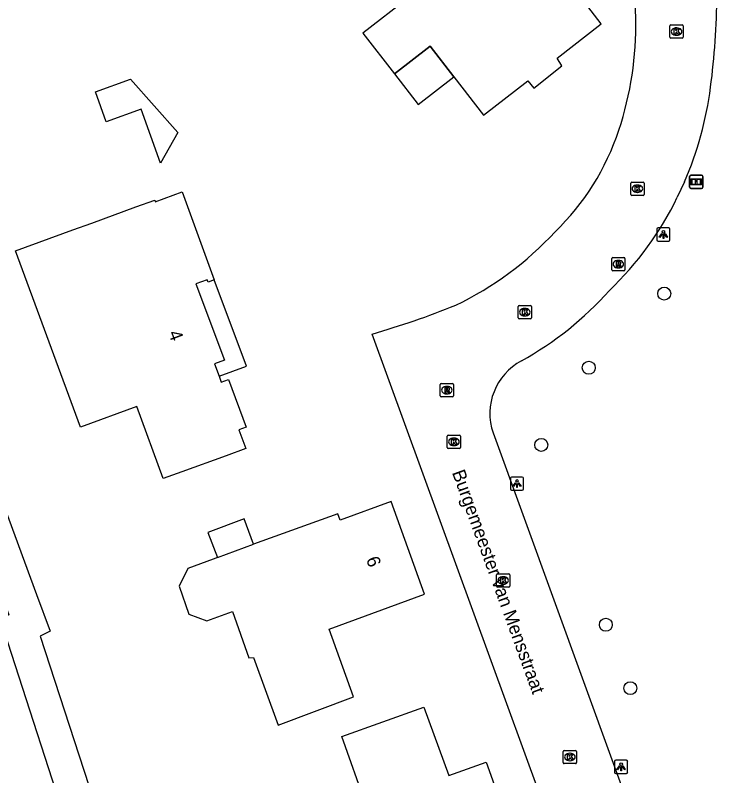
# Model space of a CAD drawing. Extents: x 159503 to 160347, y 382525 to 383272.
# Drawn here: x 159751.6 to 159804.6, y 382852.9 to 382910.4 of the extents above; entities that cross this region are included whole.
import ezdxf

# ---------------------------------------------------------------- set-up
doc = ezdxf.new("R2010")
doc.units = 0
for name, color, linetype in [('IMGEO_Boom', 7, 'Continuous'), ('IMGEO_Groenvoorziening', 7, 'Continuous'), ('IMGEO_Informatiebord', 7, 'Continuous'), ('IMGEO_Kolk', 7, 'Continuous'), ('IMGEO_Lichtpunt', 7, 'Continuous'), ('IMGEO_Openbare_ruimte_label', 7, 'Continuous'), ('IMGEO_Pand', 7, 'Continuous'), ('IMGEO_Pand_nummerreeks', 7, 'Continuous'), ('IMGEO_Pand_overbouw', 7, 'Continuous'), ('IMGEO_Rijbaan_lokaal_open', 7, 'Continuous'), ('IMGEO_Rioolput', 7, 'Continuous')]:
    doc.layers.add(name, color=color, linetype=linetype)

msp = doc.modelspace()

# ---------------------------------------------------------------- linework, layer by layer
at = {"layer": 'IMGEO_Boom'}
for centre in [(159800.667, 382889.32), (159794.962, 382883.71), (159791.37, 382877.879), (159796.25, 382864.274), (159798.106, 382859.48)]:
    msp.add_circle(centre, 0.489, dxfattribs=at)
at = {"layer": 'IMGEO_Groenvoorziening'}
for points in [[(159730.546, 382899.75), (159741.202, 382899.547), (159744.626, 382889.831), (159753.21, 382866.555), (159754.229, 382863.79), (159753.482, 382863.418), (159757.881, 382849.879)], [(159731.353, 382897.234), (159739.421, 382897.08), (159751.108, 382865.029), (159750.438, 382864.695), (159756.337, 382846.542), (159757.115, 382846.862), (159769.976, 382810.359), (159802.405, 382822.292)]]:
    msp.add_lwpolyline(points, dxfattribs=at)
at = {"layer": 'IMGEO_Informatiebord'}
for p, q in [((159802.591, 382897.372), (159802.591, 382898.172)), ((159802.591, 382898.172), (159802.591, 382897.372)), ((159802.691, 382898.272), (159803.481, 382898.272)), ((159803.481, 382898.272), (159802.691, 382898.272)), ((159803.581, 382898.172), (159803.581, 382897.372)), ((159803.581, 382897.372), (159803.581, 382898.172)), ((159803.481, 382897.272), (159802.691, 382897.272)), ((159802.691, 382897.272), (159803.481, 382897.272))]:
    msp.add_line(p, q, dxfattribs=at)
for points in [[(159802.692, 382898.004), (159803.48, 382898.004), (159803.48, 382897.54), (159802.692, 382897.54), (159802.692, 382898.004)], [(159802.757, 382897.939), (159802.757, 382897.605), (159803.032, 382897.605), (159803.033, 382897.818), (159803.137, 382897.819), (159803.138, 382897.605), (159803.415, 382897.605), (159803.415, 382897.939), (159803.139, 382897.939), (159803.139, 382897.859), (159803.033, 382897.859), (159803.033, 382897.939), (159802.757, 382897.939)]]:
    msp.add_lwpolyline(points, dxfattribs=at)
for centre, start, end in [((159802.691, 382898.172), 90, 180), ((159802.691, 382898.172), 90, 180), ((159803.481, 382898.172), 0, 90), ((159803.481, 382898.172), 360, 90), ((159802.691, 382897.372), 180, 270), ((159802.691, 382897.372), 180, 270), ((159803.481, 382897.372), 270, 0), ((159803.481, 382897.372), 270, 0)]:
    msp.add_arc(centre, 0.1, start, end, dxfattribs=at)
at = {"layer": 'IMGEO_Kolk'}
for p, q in [((159801.102, 382908.71), (159801.102, 382909.562)), ((159801.177, 382909.636), (159802.029, 382909.636)), ((159801.59, 382909.416), (159801.615, 382909.416)), ((159802.103, 382909.562), (159802.103, 382908.71)), ((159801.613, 382908.856), (159801.588, 382908.856)), ((159802.029, 382908.636), (159801.177, 382908.636)), ((159798.213, 382897.751), (159799.065, 382897.751)), ((159798.138, 382896.825), (159798.138, 382897.677)), ((159798.626, 382897.531), (159798.651, 382897.531)), ((159799.139, 382897.677), (159799.139, 382896.825)), ((159799.065, 382896.751), (159798.213, 382896.751)), ((159798.649, 382896.971), (159798.624, 382896.971)), ((159789.625, 382887.488), (159789.625, 382888.34)), ((159789.7, 382888.414), (159790.552, 382888.414)), ((159790.113, 382888.194), (159790.138, 382888.194)), ((159790.626, 382888.34), (159790.626, 382887.488)), ((159790.552, 382887.414), (159789.7, 382887.414)), ((159790.136, 382887.634), (159790.111, 382887.634)), ((159784.261, 382877.685), (159784.261, 382878.537)), ((159784.336, 382878.611), (159785.188, 382878.611)), ((159784.749, 382878.391), (159784.774, 382878.391)), ((159785.262, 382878.537), (159785.262, 382877.685)), ((159785.188, 382877.611), (159784.336, 382877.611)), ((159784.772, 382877.831), (159784.747, 382877.831)), ((159787.99, 382867.202), (159787.99, 382868.054)), ((159788.065, 382868.128), (159788.917, 382868.128)), ((159788.478, 382867.908), (159788.503, 382867.908)), ((159788.991, 382868.054), (159788.991, 382867.202)), ((159788.501, 382867.348), (159788.476, 382867.348)), ((159788.917, 382867.128), (159788.065, 382867.128)), ((159793.035, 382853.848), (159793.035, 382854.7)), ((159793.11, 382854.774), (159793.962, 382854.774)), ((159794.036, 382854.7), (159794.036, 382853.848)), ((159793.523, 382854.554), (159793.548, 382854.554)), ((159793.962, 382853.774), (159793.11, 382853.774)), ((159793.546, 382853.994), (159793.521, 382853.994))]:
    msp.add_line(p, q, dxfattribs=at)
for points in [[(159801.102, 382908.71), (159801.102, 382909.562)], [(159801.177, 382909.636), (159802.029, 382909.636)], [(159801.423, 382909.336), (159801.546, 382909.336), (159801.546, 382909.185), (159801.676, 382909.336), (159801.84, 382909.336), (159801.694, 382909.185), (159801.847, 382908.936), (159801.695, 382908.936), (159801.61, 382909.1), (159801.546, 382909.033), (159801.546, 382908.936), (159801.423, 382908.936), (159801.423, 382909.336)], [(159802.103, 382909.562), (159802.103, 382908.71)], [(159802.029, 382908.636), (159801.177, 382908.636)], [(159798.213, 382897.751), (159799.065, 382897.751)], [(159798.138, 382896.825), (159798.138, 382897.677)], [(159798.459, 382897.451), (159798.582, 382897.451), (159798.582, 382897.3), (159798.712, 382897.451), (159798.876, 382897.451), (159798.73, 382897.3), (159798.883, 382897.051), (159798.731, 382897.051), (159798.646, 382897.215), (159798.582, 382897.148), (159798.582, 382897.051), (159798.459, 382897.051), (159798.459, 382897.451)], [(159799.139, 382897.677), (159799.139, 382896.825)], [(159799.065, 382896.751), (159798.213, 382896.751)], [(159789.625, 382887.488), (159789.625, 382888.34)], [(159789.7, 382888.414), (159790.552, 382888.414)], [(159789.946, 382888.114), (159790.069, 382888.114), (159790.069, 382887.963), (159790.199, 382888.114), (159790.363, 382888.114), (159790.217, 382887.963), (159790.37, 382887.714), (159790.218, 382887.714), (159790.133, 382887.878), (159790.069, 382887.811), (159790.069, 382887.714), (159789.946, 382887.714), (159789.946, 382888.114)], [(159790.626, 382888.34), (159790.626, 382887.488)], [(159790.552, 382887.414), (159789.7, 382887.414)], [(159784.261, 382877.685), (159784.261, 382878.537)], [(159784.336, 382878.611), (159785.188, 382878.611)], [(159784.582, 382878.311), (159784.705, 382878.311), (159784.705, 382878.16), (159784.835, 382878.311), (159784.999, 382878.311), (159784.853, 382878.16), (159785.006, 382877.911), (159784.854, 382877.911), (159784.769, 382878.075), (159784.705, 382878.008), (159784.705, 382877.911), (159784.582, 382877.911), (159784.582, 382878.311)], [(159785.262, 382878.537), (159785.262, 382877.685)], [(159785.188, 382877.611), (159784.336, 382877.611)], [(159787.99, 382867.202), (159787.99, 382868.054)], [(159788.065, 382868.128), (159788.917, 382868.128)], [(159788.311, 382867.828), (159788.434, 382867.828), (159788.434, 382867.677), (159788.564, 382867.828), (159788.728, 382867.828), (159788.582, 382867.677), (159788.735, 382867.428), (159788.583, 382867.428), (159788.498, 382867.592), (159788.434, 382867.525), (159788.434, 382867.428), (159788.311, 382867.428), (159788.311, 382867.828)], [(159788.991, 382868.054), (159788.991, 382867.202)], [(159788.917, 382867.128), (159788.065, 382867.128)], [(159793.035, 382853.848), (159793.035, 382854.7)], [(159793.11, 382854.774), (159793.962, 382854.774)], [(159794.036, 382854.7), (159794.036, 382853.848)], [(159793.356, 382854.474), (159793.479, 382854.474), (159793.479, 382854.323), (159793.609, 382854.474), (159793.773, 382854.474), (159793.627, 382854.323), (159793.78, 382854.074), (159793.628, 382854.074), (159793.543, 382854.238), (159793.479, 382854.171), (159793.479, 382854.074), (159793.356, 382854.074), (159793.356, 382854.474)], [(159793.962, 382853.774), (159793.11, 382853.774)]]:
    msp.add_lwpolyline(points, dxfattribs=at)
for centre, start, end in [((159801.179, 382909.56), 91.55205, 178.44795), ((159801.179, 382909.56), 91.55205, 178.44795), ((159802.027, 382909.56), 1.55205, 88.44795), ((159802.027, 382909.56), 1.55205, 88.44795), ((159801.179, 382908.712), 181.55205, 268.44795), ((159801.179, 382908.712), 181.55205, 268.44795), ((159802.027, 382908.712), 271.55205, 358.44795), ((159802.027, 382908.712), 271.55205, 358.44795), ((159798.215, 382897.675), 91.55205, 178.44795), ((159798.215, 382897.675), 91.55205, 178.44795), ((159799.063, 382897.675), 1.55205, 88.44795), ((159799.063, 382897.675), 1.55205, 88.44795), ((159798.215, 382896.827), 181.55205, 268.44795), ((159798.215, 382896.827), 181.55205, 268.44795), ((159799.063, 382896.827), 271.55205, 358.44795), ((159799.063, 382896.827), 271.55205, 358.44795), ((159789.702, 382888.338), 91.55205, 178.44795), ((159789.702, 382888.338), 91.55205, 178.44795), ((159790.55, 382888.338), 1.55205, 88.44795), ((159790.55, 382888.338), 1.55205, 88.44795), ((159789.702, 382887.49), 181.55205, 268.44795), ((159789.702, 382887.49), 181.55205, 268.44795), ((159790.55, 382887.49), 271.55205, 358.44795), ((159790.55, 382887.49), 271.55205, 358.44795), ((159784.338, 382878.535), 91.55205, 178.44795), ((159784.338, 382878.535), 91.55205, 178.44795), ((159785.186, 382878.535), 1.55205, 88.44795), ((159785.186, 382878.535), 1.55205, 88.44795), ((159784.338, 382877.687), 181.55205, 268.44795), ((159784.338, 382877.687), 181.55205, 268.44795), ((159785.186, 382877.687), 271.55205, 358.44795), ((159785.186, 382877.687), 271.55205, 358.44795), ((159788.067, 382868.052), 91.55205, 178.44795), ((159788.067, 382868.052), 91.55205, 178.44795), ((159788.915, 382868.052), 1.55205, 88.44795), ((159788.915, 382868.052), 1.55205, 88.44795), ((159788.067, 382867.204), 181.55205, 268.44795), ((159788.067, 382867.204), 181.55205, 268.44795), ((159788.915, 382867.204), 271.55205, 358.44795), ((159788.915, 382867.204), 271.55205, 358.44795), ((159793.112, 382854.698), 91.55205, 178.44795), ((159793.112, 382854.698), 91.55205, 178.44795), ((159793.96, 382854.698), 1.55205, 88.44795), ((159793.96, 382854.698), 1.55205, 88.44795), ((159793.112, 382853.85), 181.55205, 268.44795), ((159793.112, 382853.85), 181.55205, 268.44795), ((159793.96, 382853.85), 271.55205, 358.44795), ((159793.96, 382853.85), 271.55205, 358.44795)]:
    msp.add_arc(centre, 0.0765, start, end, dxfattribs=at)
for centre, major_axis, ratio, start_param, end_param in [((159801.589, 382909.136), (-0.387, 0.002), 0.722429, 4.712389, 7.853982), ((159801.614, 382909.136), (-0.39, 0.002), 0.717154, 1.570796, 4.712389), ((159798.625, 382897.251), (-0.387, 0.002), 0.722429, 4.712389, 7.853982), ((159798.65, 382897.251), (-0.39, 0.002), 0.717154, 1.570796, 4.712389), ((159790.112, 382887.914), (-0.387, 0.002), 0.722429, 4.712389, 7.853982), ((159790.137, 382887.914), (-0.39, 0.002), 0.717154, 1.570796, 4.712389), ((159784.748, 382878.111), (-0.387, 0.002), 0.722429, 4.712389, 7.853982), ((159784.773, 382878.111), (-0.39, 0.002), 0.717154, 1.570796, 4.712389), ((159788.477, 382867.628), (-0.387, 0.002), 0.722429, 4.712389, 7.853982), ((159788.502, 382867.628), (-0.39, 0.002), 0.717154, 1.570796, 4.712389), ((159793.522, 382854.274), (-0.387, 0.002), 0.722429, 4.712389, 7.853982), ((159793.547, 382854.274), (-0.39, 0.002), 0.717154, 1.570796, 4.712389)]:
    msp.add_ellipse(centre, major_axis=major_axis, ratio=ratio, start_param=start_param, end_param=end_param, dxfattribs=at)
at = {"layer": 'IMGEO_Lichtpunt'}
for p, q in [((159801.007, 382894.286), (159800.199, 382894.286)), ((159801.007, 382894.286), (159800.199, 382894.286)), ((159800.105, 382894.191), (159800.105, 382893.384)), ((159800.105, 382894.191), (159800.105, 382893.384)), ((159801.101, 382893.384), (159801.101, 382894.191)), ((159801.101, 382893.384), (159801.101, 382894.191)), ((159800.199, 382893.29), (159801.007, 382893.29)), ((159800.199, 382893.29), (159801.007, 382893.29)), ((159789.036, 382875.352), (159789.036, 382874.545)), ((159789.036, 382875.352), (159789.036, 382874.545)), ((159789.938, 382875.447), (159789.13, 382875.447)), ((159789.938, 382875.447), (159789.13, 382875.447)), ((159790.032, 382874.545), (159790.032, 382875.352)), ((159790.032, 382874.545), (159790.032, 382875.352)), ((159789.13, 382874.451), (159789.938, 382874.451)), ((159789.13, 382874.451), (159789.938, 382874.451)), ((159797.809, 382854.034), (159797.001, 382854.034)), ((159797.809, 382854.034), (159797.001, 382854.034)), ((159796.907, 382853.939), (159796.907, 382853.132)), ((159796.907, 382853.939), (159796.907, 382853.132)), ((159797.903, 382853.132), (159797.903, 382853.939)), ((159797.903, 382853.132), (159797.903, 382853.939)), ((159797.001, 382853.038), (159797.809, 382853.038)), ((159797.001, 382853.038), (159797.809, 382853.038))]:
    msp.add_line(p, q, dxfattribs=at)
for points in [[(159800.479, 382893.855), (159800.518, 382893.827), (159800.33, 382893.565), (159800.292, 382893.592), (159800.479, 382893.855)], [(159800.581, 382893.807), (159800.628, 382893.807), (159800.628, 382893.485), (159800.581, 382893.485), (159800.581, 382893.807)], [(159800.691, 382893.827), (159800.729, 382893.854), (159800.916, 382893.592), (159800.877, 382893.564), (159800.691, 382893.827)], [(159789.41, 382875.016), (159789.449, 382874.988), (159789.261, 382874.726), (159789.223, 382874.753), (159789.41, 382875.016)], [(159789.512, 382874.968), (159789.559, 382874.968), (159789.559, 382874.646), (159789.512, 382874.646), (159789.512, 382874.968)], [(159789.622, 382874.988), (159789.66, 382875.015), (159789.847, 382874.753), (159789.808, 382874.725), (159789.622, 382874.988)], [(159797.281, 382853.603), (159797.32, 382853.575), (159797.132, 382853.313), (159797.094, 382853.34), (159797.281, 382853.603)], [(159797.383, 382853.555), (159797.43, 382853.555), (159797.43, 382853.233), (159797.383, 382853.233), (159797.383, 382853.555)], [(159797.493, 382853.575), (159797.531, 382853.602), (159797.718, 382853.34), (159797.679, 382853.312), (159797.493, 382853.575)]]:
    msp.add_lwpolyline(points, dxfattribs=at)
for centre in [(159800.604, 382893.989), (159789.535, 382875.15), (159797.406, 382853.737)]:
    msp.add_circle(centre, 0.0994, dxfattribs=at)
for centre, start, end in [((159800.199, 382894.191), 90, 180), ((159800.199, 382894.191), 90, 180), ((159801.007, 382894.191), 0, 90), ((159801.007, 382894.191), 0, 90), ((159800.199, 382893.384), 180, 270), ((159800.199, 382893.384), 180, 270), ((159801.007, 382893.384), 270, 0), ((159801.007, 382893.384), 270, 360), ((159789.13, 382875.352), 90, 180), ((159789.13, 382875.352), 90, 180), ((159789.938, 382875.352), 0, 90), ((159789.938, 382875.352), 0, 90), ((159789.13, 382874.545), 180, 270), ((159789.13, 382874.545), 180, 270), ((159789.938, 382874.545), 270, 0), ((159789.938, 382874.545), 270, 360), ((159797.001, 382853.939), 90, 180), ((159797.001, 382853.939), 90, 180), ((159797.809, 382853.939), 0, 90), ((159797.809, 382853.939), 0, 90), ((159797.001, 382853.132), 180, 270), ((159797.001, 382853.132), 180, 270), ((159797.809, 382853.132), 270, 0), ((159797.809, 382853.132), 270, 360)]:
    msp.add_arc(centre, 0.0946, start, end, dxfattribs=at)
at = {"layer": 'IMGEO_Pand'}
for points in [[(159795.905, 382909.71), (159791.354, 382915.635), (159788.06, 382913.101), (159786.645, 382912.012), (159784.784, 382914.376), (159777.868, 382909.009), (159780.26, 382905.936), (159782.968, 382908.036), (159784.766, 382905.702), (159786.989, 382902.813), (159790.348, 382905.404), (159790.798, 382904.856), (159792.921, 382906.556), (159792.571, 382907.124), (159795.905, 382909.71)], [(159762.581, 382899.19), (159761.111, 382903.271), (159758.477, 382902.322), (159757.664, 382904.58), (159760.298, 382905.529), (159763.893, 382901.5), (159762.581, 382899.19)], [(159766.629, 382890.365), (159766.17, 382890.193), (159766.103, 382890.371), (159765.26, 382890.056), (159767.416, 382884.29), (159766.669, 382883.998), (159767.007, 382883.078), (159767.172, 382882.628), (159767.726, 382882.831), (159769.048, 382879.231), (159768.494, 382879.029), (159769.017, 382877.594), (159767.542, 382877.055), (159764.194, 382875.844), (159762.78, 382875.34), (159760.774, 382880.779), (159756.533, 382879.215), (159751.617, 382892.543), (159755.938, 382894.13), (159757.376, 382894.639), (159760.708, 382895.873), (159762.138, 382896.381), (159762.182, 382896.264), (159764.216, 382897.024), (159766.629, 382890.365)], [(159766.874, 382869.353), (159766.556, 382869.235), (159764.632, 382868.52), (159763.977, 382867.195), (159764.729, 382865.078), (159766.087, 382864.568), (159768.009, 382865.276), (159769.254, 382861.771), (159769.61, 382861.8), (159771.481, 382856.693), (159777.169, 382858.827), (159775.336, 382863.944), (159782.547, 382866.591), (159780.023, 382873.596), (159776.167, 382872.186), (159775.995, 382872.653), (159769.609, 382870.363)], [(159769.609, 382870.363), (159768.897, 382872.28), (159766.164, 382871.264), (159766.874, 382869.353)], [(159766.874, 382869.353), (159769.609, 382870.363)], [(159787.196, 382853.887), (159789.832, 382846.551), (159780.443, 382843.243), (159777.762, 382850.507), (159778.141, 382850.641), (159776.283, 382855.821), (159782.488, 382858.042), (159784.384, 382852.878), (159787.196, 382853.887)]]:
    msp.add_lwpolyline(points, dxfattribs=at)
at = {"layer": 'IMGEO_Pand_overbouw'}
for points in [[(159780.26, 382905.936), (159782.065, 382903.608), (159784.766, 382905.702), (159782.968, 382908.036)], [(159766.629, 382890.365), (159766.17, 382890.193), (159766.103, 382890.371), (159765.26, 382890.056), (159767.416, 382884.29), (159766.669, 382883.998), (159767.007, 382883.078), (159769.069, 382883.838)]]:
    msp.add_lwpolyline(points, close=True, dxfattribs=at)
at = {"layer": 'IMGEO_Rijbaan_lokaal_open'}
for points in [[(159798.523, 382910.128), (159798.515, 382910.384), (159798.504, 382910.543), (159798.494, 382910.746), (159798.488, 382910.949)], [(159802.201, 382897.773), (159801.659, 382896.603)], [(159800.223, 382826.817), (159778.58, 382886.258)], [(159787.725, 382878.782), (159799.163, 382847.358), (159800.276, 382844.273)]]:
    msp.add_lwpolyline(points, dxfattribs=at)
for centre, radius, start, end in [((159750.82, 382912.013), 53.823, 352.42978, 359.88104), ((159773.358, 382909.643), 25.17, 341.55762, 1.103), ((159777.819, 382908.349), 26.577, 336.55098, 352.59185), ((159779.308, 382907.576), 18.872, 313.97884, 341.79753), ((159779.385, 382907.464), 24.781, 313.73961, 334.00564), ((159774.202, 382910.777), 24.763, 295.60595, 317.33852), ((159777.508, 382906.485), 25.453, 299.05205, 318.32008), ((159760.634, 382948.361), 64.644, 286.11789, 292.05166), ((159792.011, 382880.245), 4.529, 118.23992, 198.85096)]:
    msp.add_arc(centre, radius, start, end, dxfattribs=at)
at = {"layer": 'IMGEO_Rioolput'}
for p, q in [((159796.774, 382892.046), (159797.626, 382892.046)), ((159796.699, 382891.12), (159796.699, 382891.972)), ((159797.187, 382891.826), (159797.212, 382891.826)), ((159797.7, 382891.972), (159797.7, 382891.12)), ((159797.626, 382891.046), (159796.774, 382891.046)), ((159797.21, 382891.266), (159797.185, 382891.266)), ((159783.729, 382881.594), (159783.729, 382882.446)), ((159783.804, 382882.52), (159784.656, 382882.52)), ((159784.217, 382882.3), (159784.242, 382882.3)), ((159784.73, 382882.446), (159784.73, 382881.594)), ((159784.24, 382881.74), (159784.215, 382881.74)), ((159784.656, 382881.52), (159783.804, 382881.52))]:
    msp.add_line(p, q, dxfattribs=at)
for points in [[(159796.774, 382892.046), (159797.626, 382892.046)], [(159796.699, 382891.12), (159796.699, 382891.972)], [(159797.288, 382891.744), (159797.036, 382891.746), (159797.036, 382891.346)], [(159797.036, 382891.346), (159797.16, 382891.346), (159797.16, 382891.508), (159797.171, 382891.508)], [(159797.214, 382891.665), (159797.16, 382891.665), (159797.16, 382891.584)], [(159797.16, 382891.584), (159797.212, 382891.584)], [(159797.218, 382891.479), (159797.289, 382891.346), (159797.429, 382891.346), (159797.364, 382891.472)], [(159797.7, 382891.972), (159797.7, 382891.12)], [(159797.626, 382891.046), (159796.774, 382891.046)], [(159783.729, 382881.594), (159783.729, 382882.446)], [(159783.804, 382882.52), (159784.656, 382882.52)], [(159784.318, 382882.218), (159784.066, 382882.22), (159784.066, 382881.82)], [(159784.73, 382882.446), (159784.73, 382881.594)], [(159784.066, 382881.82), (159784.19, 382881.82), (159784.19, 382881.982), (159784.201, 382881.982)], [(159784.244, 382882.139), (159784.19, 382882.139), (159784.19, 382882.058)], [(159784.19, 382882.058), (159784.242, 382882.058)], [(159784.248, 382881.953), (159784.319, 382881.82), (159784.459, 382881.82), (159784.394, 382881.946)], [(159784.656, 382881.52), (159783.804, 382881.52)]]:
    msp.add_lwpolyline(points, dxfattribs=at)
for centre, radius, start, end in [((159796.776, 382891.97), 0.0765, 91.55205, 178.44795), ((159796.776, 382891.97), 0.0765, 91.55205, 178.44795), ((159797.624, 382891.97), 0.0765, 1.55205, 88.44795), ((159797.624, 382891.97), 0.0765, 1.55205, 88.44795), ((159797.17, 382891.455), 0.0533, 26.02933, 88.69889), ((159797.196, 382891.773), 0.19, 274.7715, 282.96867), ((159797.22, 382891.569), 0.0964, 77.00612, 93.18647), ((159797.234, 382891.626), 0.0378, 276.66336, 79.67722), ((159797.287, 382891.634), 0.109, 350.36119, 89.41601), ((159797.285, 382891.634), 0.112, 277.58423, 350.98172), ((159797.269, 382891.419), 0.108, 29.51342, 73.79051), ((159796.776, 382891.122), 0.0765, 181.55205, 268.44795), ((159796.776, 382891.122), 0.0765, 181.55205, 268.44795), ((159797.624, 382891.122), 0.0765, 271.55205, 358.44795), ((159797.624, 382891.122), 0.0765, 271.55205, 358.44795), ((159783.806, 382882.444), 0.0765, 91.55205, 178.44795), ((159783.806, 382882.444), 0.0765, 91.55205, 178.44795), ((159784.317, 382882.108), 0.109, 350.36119, 89.41601), ((159784.654, 382882.444), 0.0765, 1.55205, 88.44795), ((159784.654, 382882.444), 0.0765, 1.55205, 88.44795), ((159784.2, 382881.929), 0.0533, 26.02933, 88.69889), ((159784.226, 382882.247), 0.19, 274.7715, 282.96867), ((159784.25, 382882.043), 0.0964, 77.00612, 93.18647), ((159784.264, 382882.1), 0.0378, 276.66336, 79.67722), ((159784.315, 382882.108), 0.112, 277.58423, 350.98172), ((159784.299, 382881.893), 0.108, 29.51342, 73.79051), ((159783.806, 382881.596), 0.0765, 181.55205, 268.44795), ((159783.806, 382881.596), 0.0765, 181.55205, 268.44795), ((159784.654, 382881.596), 0.0765, 271.55205, 358.44795), ((159784.654, 382881.596), 0.0765, 271.55205, 358.44795)]:
    msp.add_arc(centre, radius, start, end, dxfattribs=at)
for centre, major_axis, ratio, start_param, end_param in [((159797.186, 382891.546), (-0.387, 0.002), 0.722429, 4.712389, 7.853982), ((159797.211, 382891.546), (-0.39, 0.002), 0.717154, 1.570796, 4.712389), ((159784.216, 382882.02), (-0.387, 0.002), 0.722429, 4.712389, 7.853982), ((159784.241, 382882.02), (-0.39, 0.002), 0.717154, 1.570796, 4.712389)]:
    msp.add_ellipse(centre, major_axis=major_axis, ratio=ratio, start_param=start_param, end_param=end_param, dxfattribs=at)

# ---------------------------------------------------------------- texts
at = {"layer": 'IMGEO_Openbare_ruimte_label'}
msp.add_text('Burgemeester van Mensstraat', height=1, rotation=289.99289, dxfattribs=at).set_placement((159784.607, 382875.79))
at = {"layer": 'IMGEO_Pand_nummerreeks'}
for s, rotation, p in [('4', 290.49449, (159763.148, 382886.342)), ('6', 289.81267, (159778.106, 382869.24))]:
    msp.add_text(s, height=1, rotation=rotation, dxfattribs=at).set_placement(p)

doc.saveas('drawing.dxf')
